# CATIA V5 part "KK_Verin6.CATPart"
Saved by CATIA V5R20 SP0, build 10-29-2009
Part number: Verin6
Bounding box of the stored display mesh (mm): x -104.996 to -71.604, y -13.926 to 4.653, z -5 to 66.399
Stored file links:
  G:\Khaled_CFAO_2011\ST2M\ST2M_GR1\msallin\Khaled\Version_Finale\KK_Verin6.CATPart
  C:\Users\Mathieu\Desktop\Think Motion\JOUG-MELEE2.CATProduct
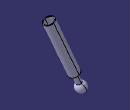
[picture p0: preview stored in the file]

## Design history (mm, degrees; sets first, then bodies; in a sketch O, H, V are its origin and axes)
External parameters (linked from other documents)
  `External.Taille du joug` = 100 mm
Set1
  Line1: linked copy from another document
  Line2: linked copy from another document
  Point1: linked copy from another document
Set2
  Plane1: type 2Lines, Element1 Line1, Element2 Line2
  Plane2: type 2Lines, Element1 Sketch1.L3, Element2 Sketch1.L5
  Point2: type Center, Curve Sketch1
  DatumSurface1
Body1 (main body)
  Sketch1 on Plane1, origin (-70.4493, -40.9938, 20.3771), H (0.5029, -0.8643, 0), V (0.2096, 0.122, 0.9701)
    line L1 (-46.3896, -17.5452) -> (-43.5951, -7.9436)
    line L2 (-43.5951, -7.9436) -> (-41.1947, -8.6422)
    line L3 (-41.1947, -8.6422) -> (-25.825, 44.1666)
    line L4 (-25.825, 44.1666) -> (-26.6252, 44.3995)
    line L5 (-26.6252, 44.3995) -> (-38.9209, 2.1524)
    line L6 (-38.9209, 2.1524) -> (-42.9215, 3.3168)
    point P7 (-42.9215, 3.3168)
    arc A1 centre (-50, -21.0042) radius 5 from (-51.3972, -25.805) to (-46.3896, -17.5452) ccw
    point P8 (-50, -21.0042)
    point P9 (-51.3972, -25.805)
    reference projected line E1 (-20, 82.0734) -> (-50, -21.0042) from Line2
    reference projected line E2 (-20, 82.0734) -> (-50, -21.0042) from Line2
    reference projected line E3 (-20, 82.0734) -> (-50, -21.0042) from Line2
    reference projected line E4 (-20, 82.0734) -> (-50, -21.0042) from Line2
    reference projected point E5 (-50, -21.0042) from Point1
    reference projected line E6 (-20, 82.0734) -> (-50, -21.0042) from Line2
    distance P7 E1 = 0
    length L3 = 55 {= `External.Taille du joug` *(7/10-1/10-1/20)}
    length L5 = 44 {= Sketch1.length(L3) *4/5}
    distance L5 E2 = 4.1667 {= `External.Taille du joug` /24}
    distance L3 E3 = 5 {= `External.Taille du joug` /20}
    length L1 = 10 {= `External.Taille du joug` /10}
    distance L1 E4 = 2.5 {= `External.Taille du joug` /40}
    distance P8 E5 = 0
    distance P9 E6 = 0
    radius A1 = 5 {= `External.Taille du joug` /20}
    perpendicularity: L2 L1
    parallelism: L3 L1, L4 L2, L5 L3, L6 L2
  Shaft1: profile Sketch1, axis Line2, angle 360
